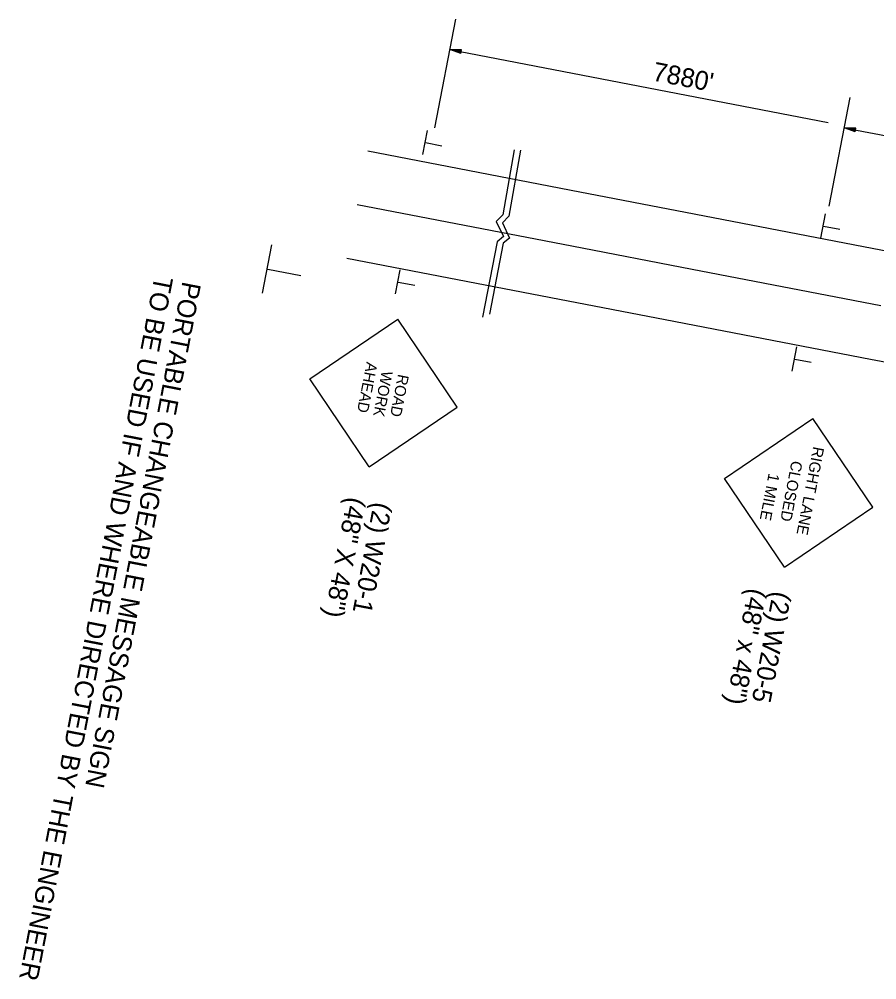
# Model space of a CAD drawing. Extents: x 606969 to 609391, y 416008 to 419486.
# Drawn here: x 606969.25 to 606996.54, y 419455.48 to 419486.03 of the extents above; entities that cross this region are included whole.
import ezdxf

# ---------------------------------------------------------------- set-up
doc = ezdxf.new("R2010")
doc.units = 0
doc.layers.add('Default', color=7, linetype='Continuous')

msp = doc.modelspace()

# ---------------------------------------------------------------- linework, layer by layer
at = {"layer": 'Default'}
for p, q in [((606983.136, 419486.027), (606982.469, 419482.57)), ((606982.95, 419485.066), (606994.991, 419482.742)), ((606983.308, 419484.94), (606982.95, 419485.066)), ((606983.329, 419485.05), (606982.95, 419485.066)), ((606983.31, 419484.949), (606983.012, 419485.054)), ((606983.328, 419485.041), (606983.012, 419485.054)), ((606983.326, 419485.031), (606983.075, 419485.042)), ((606983.312, 419484.958), (606983.075, 419485.042)), ((606983.313, 419484.967), (606983.137, 419485.03)), ((606983.324, 419485.022), (606983.137, 419485.03)), ((606983.322, 419485.013), (606983.199, 419485.018)), ((606983.315, 419484.977), (606983.199, 419485.018)), ((606983.32, 419485.003), (606983.26, 419485.006)), ((606983.317, 419484.986), (606983.26, 419485.006)), ((606983.308, 419484.94), (606983.329, 419485.05)), ((606995.684, 419483.537), (606995.016, 419480.08)), ((606982.094, 419481.724), (606982.242, 419482.492)), ((606995.498, 419482.576), (607000.622, 419481.587)), ((606995.856, 419482.45), (606995.498, 419482.576)), ((606995.877, 419482.56), (606995.498, 419482.576)), ((606995.857, 419482.459), (606995.56, 419482.564)), ((606995.875, 419482.551), (606995.56, 419482.564)), ((606995.873, 419482.541), (606995.623, 419482.552)), ((606995.859, 419482.468), (606995.623, 419482.552)), ((606995.861, 419482.477), (606995.684, 419482.54)), ((606995.872, 419482.532), (606995.684, 419482.54)), ((606995.87, 419482.523), (606995.747, 419482.528)), ((606995.863, 419482.487), (606995.747, 419482.528)), ((606995.868, 419482.513), (606995.808, 419482.516)), ((606995.865, 419482.496), (606995.808, 419482.516)), ((606995.856, 419482.45), (606995.877, 419482.56)), ((606982.179, 419482.103), (606982.703, 419482.002)), ((606980.341, 419481.844), (606987.094, 419480.54)), ((606987.094, 419480.54), (606990.457, 419479.891)), ((606980.011, 419480.137), (606986.839, 419478.819)), ((606990.457, 419479.891), (606996.998, 419478.628)), ((606994.758, 419479.067), (606994.906, 419479.835)), ((606994.843, 419479.447), (606995.367, 419479.346)), ((606976.994, 419477.314), (606977.29, 419478.85)), ((606986.839, 419478.819), (606990.661, 419478.081)), ((606979.682, 419478.43), (606986.44, 419477.125)), ((606977.164, 419478.074), (606978.213, 419477.871)), ((606981.228, 419477.289), (606981.376, 419478.057)), ((606990.661, 419478.081), (606996.668, 419476.921)), ((606981.313, 419477.669), (606981.837, 419477.568)), ((606986.44, 419477.125), (606989.803, 419476.476)), ((606978.5, 419474.593), (606981.298, 419476.487)), ((606983.192, 419473.687), (606981.298, 419476.487)), ((606989.803, 419476.476), (606996.339, 419475.214)), ((606993.843, 419474.838), (606993.991, 419475.606)), ((606993.928, 419475.217), (606994.452, 419475.116)), ((606996.339, 419475.214), (607003.114, 419473.906)), ((606980.392, 419471.793), (606978.5, 419474.593)), ((606980.392, 419471.793), (606983.192, 419473.687)), ((606991.691, 419471.416), (606994.506, 419473.328)), ((606996.415, 419470.513), (606994.506, 419473.328)), ((606993.602, 419468.602), (606991.691, 419471.416)), ((606993.602, 419468.602), (606996.415, 419470.513))]:
    msp.add_line(p, q, dxfattribs=at)
for points in [[(606985.006, 419481.876), (606984.639, 419479.805), (606984.434, 419479.598), (606984.663, 419479.113), (606984.461, 419478.949), (606983.997, 419476.547)], [(606985.206, 419481.857), (606984.834, 419479.759), (606984.629, 419479.552), (606984.857, 419479.067), (606984.656, 419478.903), (606984.22, 419476.648)]]:
    msp.add_lwpolyline(points, dxfattribs=at)

# ---------------------------------------------------------------- texts
for s, height, rotation, p in [("7880'", 0.6, 349.0745, (606989.375, 419484.084)), ('TO BE USED IF AND WHERE DIRECTED BY THE ENGINEER', 0.6, 259.0745, (606973.564, 419477.882)), ('PORTABLE CHANGEABLE MESSAGE SIGN', 0.6, 259.0745, (606974.453, 419477.711)), (' AHEAD', 0.3522, 259.0751, (606980.333, 419475.27)), ('WORK', 0.352, 259.0745, (606980.793, 419474.861)), ('ROAD', 0.3521, 259.075, (606981.31, 419474.754)), ('RIGHT LANE', 0.3544, 259.175, (606994.519, 419472.453)), ('CLOSED', 0.3543, 259.1748, (606993.832, 419472.003)), ('1 MILE', 0.3567, 259.0751, (606993.101, 419471.604)), ('(48" X 48")', 0.6, 259.0745, (606979.697, 419470.857)), ('(2) W20-1', 0.6, 259.0745, (606980.537, 419470.694)), ('(48" x 48")', 0.6, 259.0745, (606992.451, 419467.955)), ('(2) W20-5', 0.6, 259.0745, (606993.236, 419467.858))]:
    msp.add_text(s, height=height, rotation=rotation, dxfattribs=at).set_placement(p)

doc.saveas('drawing.dxf')
